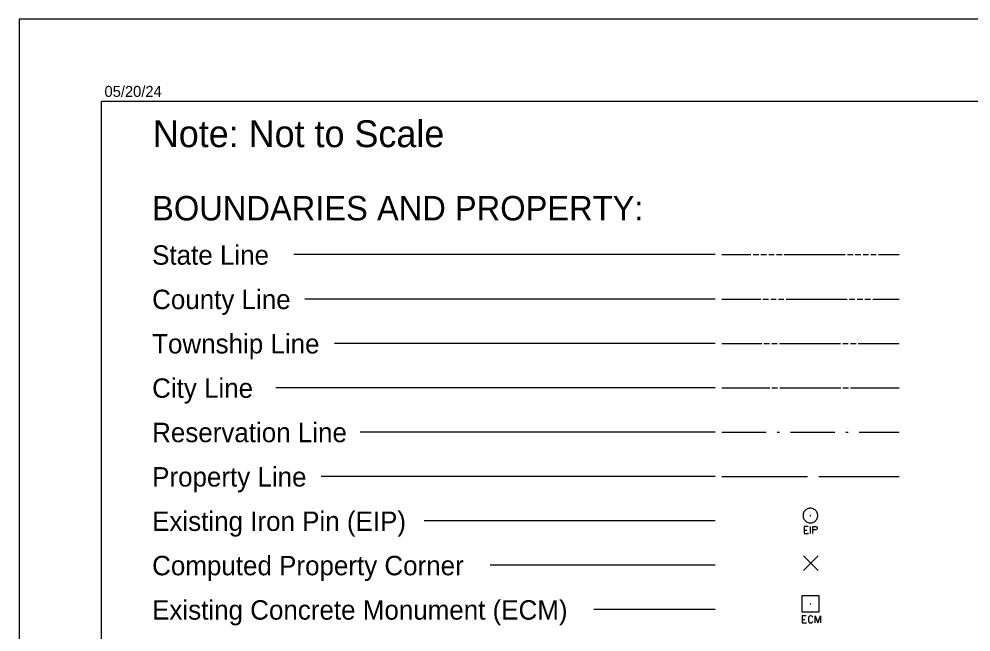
# Model space of a CAD drawing. Extents: x -0.53 to 3.34, y -0.27 to 4.33.
# Drawn here: x 0.217 to 0.939, y 3.864 to 4.328 of the extents above; entities that cross this region are included whole.
import ezdxf

# ---------------------------------------------------------------- set-up
doc = ezdxf.new("R2010")
doc.units = 0
for name, color, linetype in [('Sheet_Plan', 7, 'Continuous'), ('Sheet_Symbology', 7, 'Continuous'), ('z - Construction', 7, 'Continuous')]:
    doc.layers.add(name, color=color, linetype=linetype)

msp = doc.modelspace()

# ---------------------------------------------------------------- linework, layer by layer
at = {"layer": 'Sheet_Plan'}
for p, q in [((0.32983, 4.2785), (0.32983, 4.2785)), ((0.2799, 2.55761), (0.2799, 4.26594)), ((2.98823, 4.26594), (0.2799, 4.26594))]:
    msp.add_line(p, q, dxfattribs=at)
at = {"layer": 'Sheet_Symbology'}
for p, q in [((0.7452, 4.14983), (0.42572, 4.14983)), ((0.75003, 4.14983), (0.77223, 4.14983)), ((0.77391, 4.14983), (0.77811, 4.14983)), ((0.7798, 4.14983), (0.784, 4.14983)), ((0.78568, 4.14983), (0.78989, 4.14983)), ((0.79157, 4.14983), (0.79577, 4.14983)), ((0.79745, 4.14983), (0.8437, 4.14983)), ((0.84538, 4.14983), (0.84958, 4.14983)), ((0.85126, 4.14983), (0.85547, 4.14983)), ((0.85715, 4.14983), (0.86135, 4.14983)), ((0.86303, 4.14983), (0.86724, 4.14983)), ((0.86892, 4.14983), (0.88456, 4.14983)), ((0.7452, 4.1162), (0.43411, 4.1162)), ((0.75003, 4.1162), (0.77961, 4.1162)), ((0.78129, 4.1162), (0.78549, 4.1162)), ((0.78717, 4.1162), (0.79138, 4.1162)), ((0.79306, 4.1162), (0.79726, 4.1162)), ((0.79894, 4.1162), (0.84519, 4.1162)), ((0.84687, 4.1162), (0.85107, 4.1162)), ((0.85275, 4.1162), (0.85696, 4.1162)), ((0.85864, 4.1162), (0.86284, 4.1162)), ((0.86453, 4.1162), (0.88456, 4.1162)), ((0.7452, 4.08257), (0.45647, 4.08257)), ((0.75003, 4.08257), (0.78038, 4.08257)), ((0.78207, 4.08257), (0.78627, 4.08257)), ((0.78795, 4.08257), (0.79216, 4.08257)), ((0.79384, 4.08257), (0.84008, 4.08257)), ((0.84176, 4.08257), (0.84597, 4.08257)), ((0.84765, 4.08257), (0.85185, 4.08257)), ((0.85353, 4.08257), (0.88456, 4.08257)), ((0.7452, 4.04894), (0.41213, 4.04894)), ((0.75003, 4.04894), (0.78642, 4.04894)), ((0.7881, 4.04894), (0.7923, 4.04894)), ((0.79398, 4.04894), (0.84023, 4.04894)), ((0.84191, 4.04894), (0.84611, 4.04894)), ((0.84779, 4.04894), (0.88456, 4.04894)), ((0.7452, 4.01531), (0.47602, 4.01531)), ((0.75003, 4.01531), (0.78366, 4.01531)), ((0.79207, 4.01531), (0.79375, 4.01531)), ((0.80216, 4.01531), (0.83579, 4.01531)), ((0.8442, 4.01531), (0.84588, 4.01531)), ((0.85429, 4.01531), (0.88456, 4.01531)), ((0.7452, 3.98167), (0.44644, 3.98167)), ((0.75003, 3.98167), (0.81519, 3.98167)), ((0.8236, 3.98167), (0.88456, 3.98167)), ((0.7452, 3.94804), (0.52443, 3.94804)), ((0.81248, 3.94109), (0.81468, 3.94109)), ((0.81731, 3.93837), (0.81731, 3.94375)), ((0.8232, 3.91034), (0.81209, 3.92146)), ((0.81209, 3.91034), (0.8232, 3.92146)), ((0.7452, 3.91441), (0.57461, 3.91441)), ((0.7452, 3.88078), (0.653, 3.88078)), ((0.81095, 3.87338), (0.81315, 3.87338))]:
    msp.add_line(p, q, dxfattribs=at)
for points in [[(0.82284, 3.95208), (0.82279, 3.95279), (0.82266, 3.95346), (0.82243, 3.95413), (0.82216, 3.95476), (0.82176, 3.95534), (0.82132, 3.95588), (0.82083, 3.95637), (0.82024, 3.95677), (0.81966, 3.95713), (0.81899, 3.95735), (0.81832, 3.95753), (0.81765, 3.95762), (0.81694, 3.95762), (0.81622, 3.95753), (0.81555, 3.95735), (0.81493, 3.95713), (0.8143, 3.95677), (0.81372, 3.95637), (0.81323, 3.95588), (0.81278, 3.95534), (0.81242, 3.95476), (0.81211, 3.95413), (0.81189, 3.95346), (0.81175, 3.95279), (0.81171, 3.95208), (0.81175, 3.95136), (0.81189, 3.95069), (0.81211, 3.95002), (0.81242, 3.9494), (0.81278, 3.94882), (0.81323, 3.94828), (0.81372, 3.94779), (0.8143, 3.94739), (0.81493, 3.94703), (0.81555, 3.9468), (0.81622, 3.94663), (0.81694, 3.94654), (0.81765, 3.94654), (0.81832, 3.94663), (0.81899, 3.9468), (0.81966, 3.94703), (0.82024, 3.94739), (0.82083, 3.94779), (0.82132, 3.94828), (0.82176, 3.94882), (0.82216, 3.9494), (0.82243, 3.95002), (0.82266, 3.95069), (0.82279, 3.95136), (0.82284, 3.95208)], [(0.81738, 3.95221), (0.81725, 3.95226), (0.81716, 3.95217), (0.81712, 3.95203), (0.8172, 3.95194), (0.81734, 3.9519), (0.81743, 3.95199), (0.81747, 3.95212), (0.81738, 3.95221)], [(0.81557, 3.94375), (0.81248, 3.94375), (0.81248, 3.93837), (0.81579, 3.93837)], [(0.81909, 3.93837), (0.81909, 3.94375), (0.82125, 3.94375), (0.82189, 3.94354), (0.82244, 3.9427), (0.82244, 3.94219), (0.82193, 3.94134), (0.82125, 3.94113), (0.81909, 3.94113)], [(0.81098, 3.89136), (0.82358, 3.89136), (0.82358, 3.87876), (0.81098, 3.87876), (0.81098, 3.89136)], [(0.81725, 3.88521), (0.81719, 3.88515), (0.81719, 3.88503), (0.81732, 3.8849), (0.81744, 3.88496), (0.8175, 3.88509), (0.81738, 3.88521), (0.81725, 3.88521)], [(0.81404, 3.87605), (0.81095, 3.87605), (0.81095, 3.87067), (0.81425, 3.87067)], [(0.81912, 3.87499), (0.81845, 3.87588), (0.81777, 3.87605), (0.8173, 3.87605), (0.81667, 3.87588), (0.81595, 3.87499), (0.81578, 3.87381), (0.81578, 3.87317), (0.81578, 3.87275), (0.81582, 3.87236), (0.81595, 3.87169), (0.81667, 3.87084), (0.8173, 3.87067), (0.81768, 3.87067), (0.8184, 3.87084), (0.81912, 3.87169)], [(0.82086, 3.87067), (0.82086, 3.87605), (0.8229, 3.87067), (0.82484, 3.87605), (0.82484, 3.87067)]]:
    msp.add_lwpolyline(points, dxfattribs=at)
at = {"layer": 'z - Construction'}
for p, q in [((3.05073, 4.32844), (0.2174, 4.32844)), ((0.2174, 4.32844), (0.2174, 2.49511))]:
    msp.add_line(p, q, dxfattribs=at)

# ---------------------------------------------------------------- texts
at = {"layer": 'Sheet_Plan'}
msp.add_text('05/20/24', height=0.008333, rotation=0, dxfattribs=at).set_placement((0.28219, 4.2694))
at = {"layer": 'Sheet_Symbology'}
for s, height, p in [('Note: Not to Scale', 0.0203596, (0.31884, 4.23132)), ('BOUNDARIES AND PROPERTY:', 0.0184972, (0.31827, 4.17581)), ('State Line', 0.014714, (0.31829, 4.1422)), ('County Line', 0.0147137, (0.31829, 4.10857)), ('Township Line', 0.0147137, (0.31829, 4.07494)), ('City Line', 0.014714, (0.31829, 4.04131)), ('Reservation Line', 0.0147137, (0.31829, 4.00768)), ('Property Line', 0.0147137, (0.31829, 3.97404)), ('Existing Iron Pin (EIP)', 0.0147137, (0.31829, 3.94041)), ('Computed Property Corner', 0.0147137, (0.31829, 3.90678)), ('Existing Concrete Monument (ECM)', 0.0147137, (0.31829, 3.87315))]:
    msp.add_text(s, height=height, dxfattribs=at).set_placement(p)

doc.saveas('drawing.dxf')
